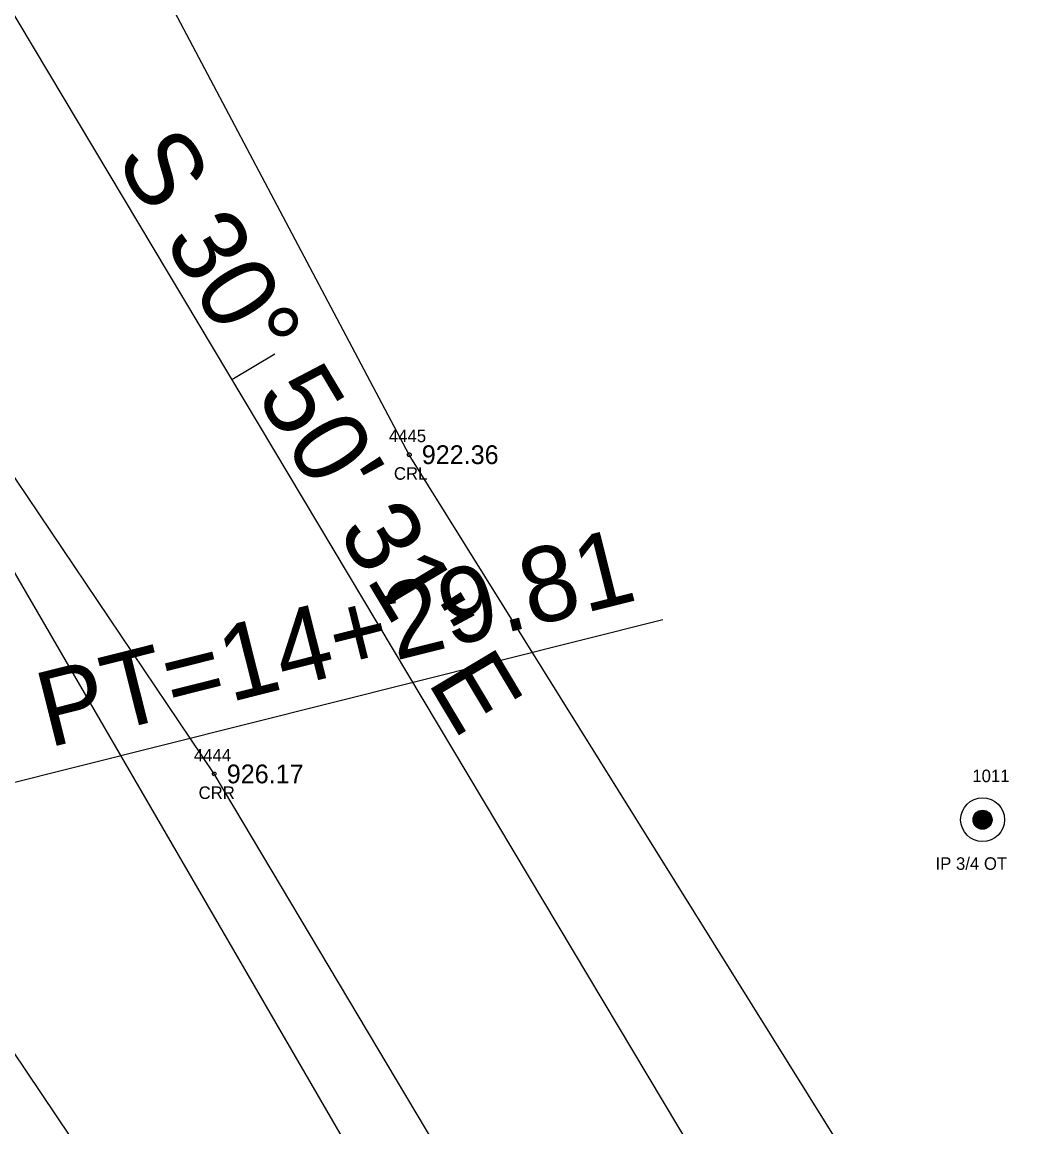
# Model space of a CAD drawing. Extents: x 1575382 to 1578175, y 1099175 to 1101955.
# Drawn here: x 1576881.9 to 1576961.2, y 1101074.3 to 1101162.6 of the extents above; entities that cross this region are included whole.
import ezdxf

# ---------------------------------------------------------------- set-up
doc = ezdxf.new("R2010")
doc.units = 0
for name, color, linetype in [('RD_EX_DV_Prop_txCode', 7, 'Continuous'), ('RD_EX_DV_PropPin', 7, 'Continuous'), ('RD_EX_H2O', 7, 'Continuous'), ('RD_EX_H2O_txCode', 7, 'Continuous'), ('RD_EX_TX_H2O_ELEV', 7, 'Continuous'), ('RD_EX_VEG', 7, 'Continuous'), ('RD_HC_Cl', 7, 'Continuous'), ('RD_HC_Data', 7, 'Continuous'), ('RD_HC_Data_Tic', 7, 'Continuous'), ('RD_SMD_Locator', 7, 'Continuous')]:
    doc.layers.add(name, color=color, linetype=linetype)

msp = doc.modelspace()

# ---------------------------------------------------------------- linework, layer by layer
at = {"layer": 'RD_EX_DV_PropPin'}
for p, q in [((1576958.125, 1101098.271), (1576958.125, 1101099.435)), ((1576958.16, 1101098.243), (1576958.16, 1101099.463)), ((1576958.195, 1101098.218), (1576958.195, 1101099.487)), ((1576958.23, 1101098.196), (1576958.23, 1101099.509)), ((1576958.265, 1101098.177), (1576958.265, 1101099.528)), ((1576958.3, 1101098.16), (1576958.3, 1101099.545)), ((1576958.335, 1101098.145), (1576958.335, 1101099.56)), ((1576958.37, 1101098.132), (1576958.37, 1101099.573)), ((1576958.405, 1101098.121), (1576958.405, 1101099.584)), ((1576958.44, 1101098.112), (1576958.44, 1101099.593)), ((1576958.475, 1101098.105), (1576958.475, 1101099.601)), ((1576958.51, 1101098.099), (1576958.51, 1101099.606)), ((1576958.545, 1101098.095), (1576958.545, 1101099.61)), ((1576958.58, 1101098.092), (1576958.58, 1101099.613)), ((1576958.615, 1101098.092), (1576958.615, 1101099.614)), ((1576958.65, 1101098.092), (1576958.65, 1101099.613)), ((1576958.685, 1101098.095), (1576958.685, 1101099.61)), ((1576958.72, 1101098.099), (1576958.72, 1101099.606)), ((1576958.755, 1101098.105), (1576958.755, 1101099.601)), ((1576958.79, 1101098.112), (1576958.79, 1101099.593)), ((1576958.825, 1101098.121), (1576958.825, 1101099.584)), ((1576958.86, 1101098.132), (1576958.86, 1101099.573)), ((1576958.895, 1101098.145), (1576958.895, 1101099.56)), ((1576958.931, 1101098.16), (1576958.931, 1101099.545)), ((1576958.966, 1101098.177), (1576958.966, 1101099.528)), ((1576959.001, 1101098.196), (1576959.001, 1101099.509)), ((1576959.036, 1101098.218), (1576959.036, 1101099.487)), ((1576959.071, 1101098.243), (1576959.071, 1101099.463)), ((1576959.106, 1101098.271), (1576959.106, 1101099.435)), ((1576957.88, 1101098.657), (1576957.88, 1101099.049)), ((1576957.915, 1101098.555), (1576957.915, 1101099.151)), ((1576957.95, 1101098.483), (1576957.95, 1101099.222)), ((1576957.985, 1101098.426), (1576957.985, 1101099.279)), ((1576958.02, 1101098.379), (1576958.02, 1101099.327)), ((1576958.055, 1101098.338), (1576958.055, 1101099.368)), ((1576958.09, 1101098.302), (1576958.09, 1101099.403)), ((1576959.141, 1101098.302), (1576959.141, 1101099.403)), ((1576959.176, 1101098.338), (1576959.176, 1101099.368)), ((1576959.211, 1101098.379), (1576959.211, 1101099.327)), ((1576959.246, 1101098.426), (1576959.246, 1101099.279)), ((1576959.281, 1101098.483), (1576959.281, 1101099.222)), ((1576959.316, 1101098.555), (1576959.316, 1101099.151)), ((1576959.351, 1101098.657), (1576959.351, 1101099.049))]:
    msp.add_line(p, q, dxfattribs=at)
for radius in [1.75, 0.761]:
    msp.add_circle((1576958.615, 1101098.853), radius, dxfattribs=at)
at = {"layer": 'RD_EX_H2O'}
for points in [[(1577058.83, 1100906.759), (1577066.568, 1100916.083), (1577041.89, 1100951.367), (1577010.39, 1100991.567), (1576974.354, 1101030.665), (1576949.205, 1101069.642), (1576912.822, 1101128.006), (1576885.934, 1101178.757), (1576854.06, 1101233.124)], [(1577042.97, 1100897.204), (1577038.115, 1100899.956), (1577014.743, 1100933.184), (1576984.891, 1100969.371), (1576955.449, 1101012.576), (1576924.867, 1101056.147), (1576897.244, 1101102.51), (1576868.308, 1101145.43), (1576840.707, 1101206.599)]]:
    msp.add_lwpolyline(points, dxfattribs=at)
at = {"layer": 'RD_EX_VEG'}
for points in [[(1576850.621, 1101171.41), (1576930.104, 1101034.469), (1577038.251, 1100883.779), (1577074.138, 1100918.209), (1577030.741, 1100978.52)], [(1576842.661, 1101165.203), (1576856.324, 1101117.296), (1576901.07, 1101050.702), (1576926.345, 1101005.763), (1576957.585, 1100975.469), (1576985.787, 1100943.994), (1577005.951, 1100901.315), (1577049.501, 1100868.209), (1577075.374, 1100845.032), (1577056.225, 1100809.989)]]:
    msp.add_lwpolyline(points, dxfattribs=at)
at = {"layer": 'RD_HC_Cl'}
msp.add_line((1576847.383, 1101219.861), (1576958.935, 1101033.042), dxfattribs=at)
msp.add_arc((1577257.909, 1101196.452), 450, 194.10128, 235.13175, dxfattribs=at)
at = {"layer": 'RD_HC_Data'}
msp.add_line((1576821.469, 1101086.816), (1576933.079, 1101114.853), dxfattribs=at)
at = {"layer": 'RD_HC_Data_Tic'}
msp.add_line((1576898.65, 1101134.003), (1576902.085, 1101136.053), dxfattribs=at)
at = {"layer": 'RD_SMD_Locator'}
for centre in [(1576912.822, 1101128.006), (1576897.244, 1101102.51), (1576958.615, 1101098.853)]:
    msp.add_circle(centre, 0.15, dxfattribs=at)

# ---------------------------------------------------------------- texts
at = {"layer": 'RD_EX_DV_Prop_txCode'}
for s, p in [('1011', (1576957.797, 1101101.853)), ('IP 3/4 OT', (1576954.859, 1101094.853))]:
    msp.add_text(s, height=1, dxfattribs=at).set_placement(p)
at = {"layer": 'RD_EX_H2O_txCode'}
for s, p in [('4445', (1576911.192, 1101129.006)), ('CRL', (1576911.594, 1101126.006)), ('4444', (1576895.614, 1101103.51)), ('CRR', (1576895.992, 1101100.51))]:
    msp.add_text(s, height=1, dxfattribs=at).set_placement(p)
at = {"layer": 'RD_EX_TX_H2O_ELEV'}
for s, p in [('922.36', (1576913.822, 1101127.256)), ('926.17', (1576898.244, 1101101.76))]:
    msp.add_text(s, height=1.5, dxfattribs=at).set_placement(p)
at = {"layer": 'RD_HC_Data'}
for s, rotation, p in [('S 30%%d 50\' 31" E', 300.84188, (1576889.28, 1101151.647)), ('PT=14+29.81', 14.10128, (1576884.023, 1101104.592))]:
    msp.add_text(s, height=6, rotation=rotation, dxfattribs=at).set_placement(p)

doc.saveas('drawing.dxf')
